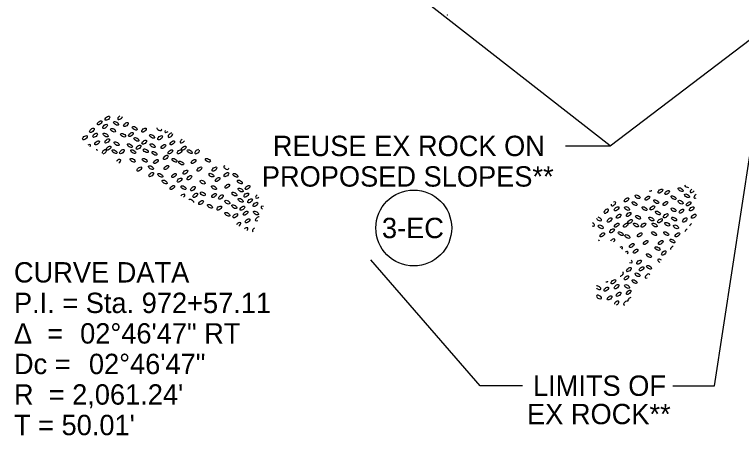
# Model space of a CAD drawing. Extents: x 1785 to 2465, y -264 to 295.
# Drawn here: x 2138.7 to 2238.8, y -70.4 to -12.5 of the extents above; entities that cross this region are included whole.
import ezdxf

# ---------------------------------------------------------------- set-up
doc = ezdxf.new("R2010")
doc.units = 0
for name, color, linetype in [('DR_P_Culvert', 7, 'Continuous'), ('DR_X_Erosion_Control', 7, 'Continuous'), ('PV_P_Shoulder', 7, 'Continuous'), ('RW_X_CL_100_Curve_Data', 7, 'Continuous'), ('TX_P_1', 7, 'Continuous')]:
    doc.layers.add(name, color=color, linetype=linetype)

msp = doc.modelspace()

# ---------------------------------------------------------------- linework, layer by layer
at = {"layer": 'DR_P_Culvert'}
for p, q in [((2235.1, -63.51), (2240.05, -31.26)), ((2202.85, -63.51), (2187.78, -46.18)), ((2208.64, -63.51), (2202.85, -63.51)), ((2229.37, -63.51), (2235.1, -63.51))]:
    msp.add_line(p, q, dxfattribs=at)
at = {"layer": 'DR_X_Erosion_Control'}
for centre, major_axis in [((2151.53, -26.73), (0.296, 0.243)), ((2150.46, -27.35), (0.296, 0.243)), ((2151.2, -27.84), (0.296, 0.243)), ((2152.72, -27.43), (0.33, -0.195)), ((2154.07, -27.6), (0.296, 0.243)), ((2155.29, -28.1), (0.33, -0.195)), ((2149.4, -28.39), (0.296, 0.243)), ((2149.84, -29.07), (0.296, 0.243)), ((2151.28, -29.04), (0.33, -0.195)), ((2152.31, -28.37), (0.33, -0.195)), ((2153.69, -29.06), (0.33, -0.195)), ((2154.76, -28.96), (0.296, 0.243)), ((2156.56, -28.35), (0.296, 0.243)), ((2157.68, -29.22), (0.33, -0.195)), ((2148.42, -29.4), (0.296, 0.243)), ((2150.11, -30.11), (0.296, 0.243)), ((2151.5, -29.85), (0.296, 0.243)), ((2152.8, -30.23), (0.33, -0.195)), ((2155.52, -29.64), (0.33, -0.195)), ((2156.6, -30.03), (0.296, 0.243)), ((2158.77, -29.4), (0.296, 0.243)), ((2160.46, -30.11), (0.296, 0.243)), ((2151.69, -30.84), (0.296, 0.243)), ((2153.53, -31.32), (0.296, 0.243)), ((2154.62, -30.49), (0.33, -0.195)), ((2155.81, -30.72), (0.296, 0.243)), ((2156.81, -31.2), (0.33, -0.195)), ((2157.76, -30.49), (0.33, -0.195)), ((2159.23, -30.62), (0.296, 0.243)), ((2160.2, -31.34), (0.296, 0.243)), ((2161.45, -31.33), (0.296, 0.243)), ((2162.04, -30.84), (0.296, 0.243)), ((2152.51, -31.32), (0.33, -0.195)), ((2155.08, -31.32), (0.33, -0.195)), ((2158.01, -31.56), (0.33, -0.195)), ((2159.56, -32.1), (0.296, 0.243)), ((2162.86, -31.32), (0.33, -0.195)), ((2155, -32.5), (0.33, -0.195)), ((2156.67, -32.5), (0.33, -0.195)), ((2158.21, -32.67), (0.296, 0.243)), ((2160.76, -32.51), (0.33, -0.195)), ((2161.68, -32.89), (0.33, -0.195)), ((2163.38, -32.67), (0.296, 0.243)), ((2165.35, -32.5), (0.33, -0.195)), ((2155.91, -33.71), (0.296, 0.243)), ((2157.52, -33.51), (0.33, -0.195)), ((2159.64, -33.5), (0.296, 0.243)), ((2162.27, -34.13), (0.296, 0.243)), ((2164.19, -33.71), (0.296, 0.243)), ((2166.26, -33.71), (0.296, 0.243)), ((2157.56, -34.48), (0.296, 0.243)), ((2158.8, -34.57), (0.33, -0.195)), ((2160.69, -34.6), (0.296, 0.243)), ((2161.45, -35.23), (0.296, 0.243)), ((2162.81, -34.9), (0.296, 0.243)), ((2165.82, -34.55), (0.33, -0.195)), ((2166.69, -35.16), (0.296, 0.243)), ((2167.91, -34.48), (0.296, 0.243)), ((2169.15, -34.57), (0.33, -0.195)), ((2159.4, -35.49), (0.33, -0.195)), ((2160.46, -36.25), (0.296, 0.243)), ((2162, -36.27), (0.33, -0.195)), ((2164.63, -35.52), (0.33, -0.195)), ((2166.2, -36.27), (0.33, -0.195)), ((2168.02, -36.06), (0.296, 0.243)), ((2169.75, -35.49), (0.33, -0.195)), ((2170.81, -36.25), (0.296, 0.243)), ((2163.29, -36.41), (0.296, 0.243)), ((2163.62, -37.33), (0.296, 0.243)), ((2164.66, -37.12), (0.33, -0.195)), ((2169, -37.16), (0.33, -0.195)), ((2169.87, -36.6), (0.33, -0.195)), ((2170.63, -37.29), (0.296, 0.243)), ((2227.63, -36.74), (0.296, 0.243)), ((2228.57, -36.94), (0.296, 0.243)), ((2230.42, -36.54), (0.33, -0.195)), ((2164.42, -38.33), (0.296, 0.243)), ((2166.21, -37.36), (0.296, 0.243)), ((2167.15, -37.56), (0.296, 0.243)), ((2168.03, -38.27), (0.33, -0.195)), ((2169.87, -38.01), (0.33, -0.195)), ((2171.16, -38.07), (0.296, 0.243)), ((2222.97, -37.95), (0.296, 0.243)), ((2224.49, -37.53), (0.33, -0.195)), ((2225.84, -37.71), (0.296, 0.243)), ((2227.06, -38.21), (0.33, -0.195)), ((2229.45, -37.65), (0.33, -0.195)), ((2230.42, -38.27), (0.33, -0.195)), ((2231.29, -37.39), (0.33, -0.195)), ((2165.64, -38.83), (0.33, -0.195)), ((2166.91, -39.08), (0.296, 0.243)), ((2169, -38.89), (0.33, -0.195)), ((2170.1, -39.11), (0.296, 0.243)), ((2171.9, -38.57), (0.296, 0.243)), ((2221.61, -39.17), (0.296, 0.243)), ((2223.05, -39.14), (0.33, -0.195)), ((2224.08, -38.47), (0.33, -0.195)), ((2225.46, -39.16), (0.33, -0.195)), ((2226.53, -39.06), (0.296, 0.243)), ((2228.33, -38.46), (0.296, 0.243)), ((2231.52, -38.49), (0.296, 0.243)), ((2231.96, -39.17), (0.296, 0.243)), ((2168.03, -39.94), (0.33, -0.195)), ((2169.12, -40.13), (0.296, 0.243)), ((2170.54, -39.79), (0.296, 0.243)), ((2171.98, -39.77), (0.33, -0.195)), ((2221.88, -40.21), (0.296, 0.243)), ((2223.27, -39.95), (0.296, 0.243)), ((2227.29, -39.75), (0.33, -0.195)), ((2228.37, -40.13), (0.296, 0.243)), ((2229.45, -39.32), (0.33, -0.195)), ((2230.54, -39.5), (0.296, 0.243)), ((2232.23, -40.21), (0.296, 0.243)), ((2170.81, -40.83), (0.296, 0.243)), ((2220.65, -40.72), (0.296, 0.243)), ((2223.46, -40.94), (0.296, 0.243)), ((2224.57, -40.34), (0.33, -0.195)), ((2226.39, -40.59), (0.33, -0.195)), ((2227.58, -40.82), (0.296, 0.243)), ((2228.58, -41.3), (0.33, -0.195)), ((2229.53, -40.59), (0.33, -0.195)), ((2231, -40.72), (0.296, 0.243)), ((2219.43, -41.66), (0.33, -0.195)), ((2220.98, -42.2), (0.296, 0.243)), ((2221.62, -41.44), (0.296, 0.243)), ((2222.87, -41.43), (0.296, 0.243)), ((2224.28, -41.42), (0.33, -0.195)), ((2225.3, -41.42), (0.296, 0.243)), ((2226.85, -41.42), (0.33, -0.195)), ((2229.78, -41.66), (0.33, -0.195)), ((2219.63, -42.77), (0.296, 0.243)), ((2222.18, -42.61), (0.33, -0.195)), ((2223.1, -42.99), (0.33, -0.195)), ((2224.8, -42.77), (0.296, 0.243)), ((2226.77, -42.6), (0.33, -0.195)), ((2228.44, -42.6), (0.33, -0.195)), ((2229.98, -42.77), (0.296, 0.243)), ((2223.69, -44.23), (0.296, 0.243)), ((2225.61, -43.82), (0.296, 0.243)), ((2227.68, -43.82), (0.296, 0.243)), ((2229.29, -43.61), (0.33, -0.195)), ((2224.23, -45), (0.296, 0.243)), ((2227.24, -44.65), (0.33, -0.195)), ((2228.11, -45.26), (0.296, 0.243)), ((2226.05, -45.62), (0.33, -0.195)), ((2224.71, -46.51), (0.296, 0.243)), ((2226.08, -47.22), (0.33, -0.195)), ((2223.3, -47.55), (0.296, 0.243)), ((2224.49, -48.26), (0.33, -0.195)), ((2225.04, -47.43), (0.296, 0.243)), ((2221.17, -49.21), (0.296, 0.243)), ((2222.97, -48.67), (0.296, 0.243)), ((2224.08, -49.19), (0.33, -0.195)), ((2220.19, -50.23), (0.296, 0.243)), ((2221.61, -49.89), (0.296, 0.243)), ((2223.05, -49.87), (0.33, -0.195)), ((2221.88, -50.94), (0.296, 0.243)), ((2223.27, -50.67), (0.296, 0.243)), ((2220.65, -51.44), (0.296, 0.243))]:
    msp.add_ellipse(centre, major_axis=major_axis, ratio=0.503326, dxfattribs=at)
for centre, major_axis, start_param, end_param in [((2153.27, -26.61), (0.296, 0.243), 1.235809, 5.66974), ((2158.65, -28.17), (0.33, -0.195), 3.415836, 6.283185), ((2158.65, -28.17), (0.33, -0.195), 0, 0.560351), ((2159.75, -28.39), (0.296, 0.243), 2.191658, 4.71389), ((2160.19, -29.07), (0.296, 0.243), 0.507601, 6.119269), ((2161.85, -29.85), (0.296, 0.243), 1.342096, 5.284773), ((2148.88, -30.62), (0.296, 0.243), 0, 1.287845), ((2148.88, -30.62), (0.296, 0.243), 5.369661, 6.283185), ((2151.1, -31.33), (0.296, 0.243), 0, 2.894204), ((2149.85, -31.34), (0.296, 0.243), 0, 0.779659), ((2149.85, -31.34), (0.296, 0.243), 5.877847, 6.283185), ((2151.1, -31.33), (0.296, 0.243), 3.763303, 6.283185), ((2163.88, -31.32), (0.296, 0.243), 0.587242, 6.039627), ((2153.03, -32.67), (0.296, 0.243), 0, 2.126384), ((2153.03, -32.67), (0.296, 0.243), 4.531122, 6.283185), ((2167.87, -33.51), (0.33, -0.195), 2.479706, 6.283185), ((2167.87, -33.51), (0.33, -0.195), 0, 0.594281), ((2231.29, -35.98), (0.33, -0.195), 3.802203, 5.666175), ((2226.08, -36.5), (0.33, -0.195), 4.994504, 6.283185), ((2226.08, -36.5), (0.33, -0.195), 0, 0.362456), ((2232.05, -36.67), (0.296, 0.243), 1.485391, 5.172307), ((2161.88, -37.45), (0.296, 0.243), 0, 1.970599), ((2161.88, -37.45), (0.296, 0.243), 4.733881, 6.283185), ((2163.07, -38.16), (0.33, -0.195), 0.146686, 3.203536), ((2172.23, -37.45), (0.296, 0.243), 1.432637, 4.825187), ((2232.58, -37.45), (0.296, 0.243), 1.25944, 4.239151), ((2173.01, -39.09), (0.33, -0.195), 1.857674, 4.564955), ((2221.17, -38.49), (0.296, 0.243), 2.376187, 6.283185), ((2221.17, -38.49), (0.296, 0.243), 0, 1.112653), ((2220.19, -39.5), (0.296, 0.243), 1.860384, 6.283185), ((2220.19, -39.5), (0.296, 0.243), 0, 1.628456), ((2172.2, -40.57), (0.296, 0.243), 0.421728, 4.341249), ((2219.18, -40.59), (0.33, -0.195), 3.797872, 6.283185), ((2219.18, -40.59), (0.33, -0.195), 0, 2.21803), ((2169.58, -41.34), (0.296, 0.243), 0, 2.302953), ((2169.58, -41.34), (0.296, 0.243), 4.401528, 6.283185), ((2170.55, -42.06), (0.296, 0.243), 0, 1.759204), ((2170.55, -42.06), (0.296, 0.243), 4.945277, 6.283185), ((2171.8, -42.05), (0.296, 0.243), 1.261061, 3.501916), ((2218.23, -41.3), (0.33, -0.195), 5.004764, 6.283185), ((2218.23, -41.3), (0.33, -0.195), 0, 1.727315), ((2231.33, -42.2), (0.296, 0.243), 1.20419, 2.683506), ((2231.97, -41.44), (0.296, 0.243), 1.290018, 2.597678), ((2218.94, -43.61), (0.33, -0.195), 0.756586, 1.357846), ((2221.06, -43.6), (0.296, 0.243), 0, 2.257809), ((2221.06, -43.6), (0.296, 0.243), 4.757086, 6.283185), ((2222.11, -44.7), (0.296, 0.243), 0, 1.341857), ((2222.11, -44.7), (0.296, 0.243), 5.105314, 6.283185), ((2222.87, -45.33), (0.296, 0.243), 0, 1.416166), ((2229.33, -44.58), (0.296, 0.243), 0.999193, 2.888503), ((2222.87, -45.33), (0.296, 0.243), 5.031006, 6.283185), ((2223.42, -46.37), (0.33, -0.195), 4.935316, 6.283185), ((2223.42, -46.37), (0.33, -0.195), 0, 1.275823), ((2227.62, -46.37), (0.33, -0.195), 1.315701, 4.81096), ((2222.23, -48.18), (0.296, 0.243), 3.89704, 6.283185), ((2222.23, -48.18), (0.296, 0.243), 0, 0.274826), ((2225.84, -48.43), (0.296, 0.243), 0, 4.250371), ((2225.84, -48.43), (0.296, 0.243), 5.92051, 6.283185), ((2219.1, -50.04), (0.33, -0.195), 0, 2.725664), ((2220.07, -48.99), (0.33, -0.195), 5.109765, 6.283185), ((2220.07, -48.99), (0.33, -0.195), 0, 0.349249), ((2219.1, -50.04), (0.33, -0.195), 4.135698, 6.283185), ((2219.18, -51.31), (0.33, -0.195), 0, 3.275955), ((2219.18, -51.31), (0.33, -0.195), 3.585407, 6.283185), ((2221.62, -52.16), (0.296, 0.243), 0, 2.703694), ((2221.62, -52.16), (0.296, 0.243), 4.286623, 6.283185), ((2222.87, -52.15), (0.296, 0.243), 0.062461, 3.825235), ((2223.46, -51.66), (0.296, 0.243), 0.810133, 3.077564)]:
    msp.add_ellipse(centre, major_axis=major_axis, ratio=0.503326, start_param=start_param, end_param=end_param, dxfattribs=at)
at = {"layer": 'PV_P_Shoulder'}
msp.add_open_spline([(2198.32, -12.53), (2198.34, -12.52), (2198.36, -12.5), (2198.38, -12.49)], degree=2, dxfattribs=at)
at = {"layer": 'TX_P_1'}
for p, q in [((2220.74, -30.53), (2249.66, -8.53)), ((2220.74, -30.53), (2194.63, -10.1)), ((2214.59, -30.53), (2220.74, -30.53))]:
    msp.add_line(p, q, dxfattribs=at)
msp.add_circle((2193.69, -41.82), 5.22, dxfattribs=at)

# ---------------------------------------------------------------- texts
at = {"layer": 'DR_P_Culvert'}
for s, p in [('LIMITS OF', (2210.1, -64.91)), ('EX ROCK**', (2209.28, -68.81))]:
    msp.add_text(s, height=2.8, dxfattribs=at).set_placement(p)
at = {"layer": 'RW_X_CL_100_Curve_Data'}
for s, p in [('CURVE DATA', (2138.66, -49.32)), ('P.I. = Sta. 972+57.11', (2138.66, -53.52)), ('Δ  = ', (2138.66, -57.72)), ('02°46\'47" RT', (2147.77, -57.72)), ('Dc = ', (2138.66, -61.92)), ('02°46\'47"', (2148.98, -61.92)), ("R  = 2,061.24'", (2138.66, -66.12)), ("T = 50.01'", (2138.66, -70.32))]:
    msp.add_text(s, height=2.8, dxfattribs=at).set_placement(p)
at = {"layer": 'TX_P_1'}
for s, p in [('REUSE EX ROCK ON', (2174.29, -31.93)), ('PROPOSED SLOPES**', (2172.78, -36.13)), ('3-EC', (2189.31, -43.22))]:
    msp.add_text(s, height=2.8, dxfattribs=at).set_placement(p)

doc.saveas('drawing.dxf')
